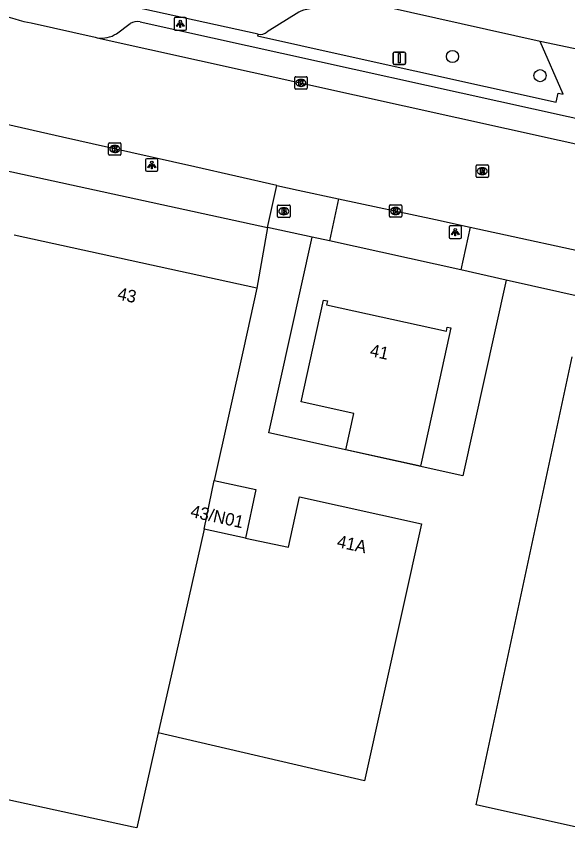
# Model space of a CAD drawing. Extents: x 162172 to 163187, y 382874 to 383684.
# Drawn here: x 162616.1 to 162660.4, y 383101.7 to 383167.1 of the extents above; entities that cross this region are included whole.
import ezdxf

# ---------------------------------------------------------------- set-up
doc = ezdxf.new("R2010")
doc.units = 0
for name, color, linetype in [('IMGEO_Boom', 7, 'Continuous'), ('IMGEO_Brandkraan', 7, 'Continuous'), ('IMGEO_Hek', 7, 'Continuous'), ('IMGEO_Kolk', 7, 'Continuous'), ('IMGEO_Lichtpunt', 7, 'Continuous'), ('IMGEO_Muur', 7, 'Continuous'), ('IMGEO_Pand', 7, 'Continuous'), ('IMGEO_Pand_nummerreeks', 7, 'Continuous'), ('IMGEO_Parkeervlak_open', 7, 'Continuous'), ('IMGEO_Rijbaan_lokaal_open', 7, 'Continuous'), ('IMGEO_Rioolput', 7, 'Continuous'), ('IMGEO_Verkeersbordpaal', 7, 'Continuous'), ('IMGEO_Voetpad_open', 7, 'Continuous')]:
    doc.layers.add(name, color=color, linetype=linetype)

msp = doc.modelspace()

# ---------------------------------------------------------------- linework, layer by layer
at = {"layer": 'IMGEO_Boom'}
for centre in [(162651.15, 383163.911), (162658.185, 383162.367)]:
    msp.add_circle(centre, 0.489, dxfattribs=at)
at = {"layer": 'IMGEO_Brandkraan'}
for p, q in [((162637.091, 383151.046), (162637.091, 383151.898)), ((162637.166, 383151.972), (162638.018, 383151.972)), ((162637.579, 383151.752), (162637.604, 383151.752)), ((162638.092, 383151.898), (162638.092, 383151.046)), ((162637.602, 383151.192), (162637.577, 383151.192)), ((162638.018, 383150.972), (162637.166, 383150.972))]:
    msp.add_line(p, q, dxfattribs=at)
for points in [[(162637.091, 383151.046), (162637.091, 383151.898)], [(162637.166, 383151.972), (162638.018, 383151.972)], [(162638.092, 383151.898), (162638.092, 383151.046)], [(162637.439, 383151.672), (162637.439, 383151.272), (162637.652, 383151.272)], [(162637.67, 383151.672), (162637.439, 383151.672)], [(162637.618, 383151.591), (162637.564, 383151.591), (162637.564, 383151.515)], [(162637.564, 383151.515), (162637.617, 383151.515)], [(162637.626, 383151.439), (162637.564, 383151.439), (162637.564, 383151.358)], [(162637.564, 383151.358), (162637.626, 383151.358)], [(162638.018, 383150.972), (162637.166, 383150.972)]]:
    msp.add_lwpolyline(points, dxfattribs=at)
for centre, radius, start, end in [((162637.168, 383151.896), 0.0765, 91.55205, 178.44795), ((162637.168, 383151.896), 0.0765, 91.55205, 178.44795), ((162638.016, 383151.896), 0.0765, 1.55205, 88.44795), ((162638.016, 383151.896), 0.0765, 1.55205, 88.44795), ((162637.619, 383151.553), 0.0379, 267.82845, 90.93552), ((162637.627, 383151.398), 0.0404, 269.87594, 90.50774), ((162637.658, 383151.523), 0.251, 268.66757, 293.53466), ((162637.674, 383151.527), 0.145, 59.4692, 91.53667), ((162637.699, 383151.574), 0.0922, 285.51372, 58.15012), ((162637.704, 383151.382), 0.105, 301.31148, 78.98903), ((162637.168, 383151.048), 0.0765, 181.55205, 268.44795), ((162637.168, 383151.048), 0.0765, 181.55205, 268.44795), ((162638.016, 383151.048), 0.0765, 271.55205, 358.44795), ((162638.016, 383151.048), 0.0765, 271.55205, 358.44795)]:
    msp.add_arc(centre, radius, start, end, dxfattribs=at)
for centre, major_axis, ratio, start_param, end_param in [((162637.578, 383151.472), (-0.387, 0.002), 0.722429, 4.712389, 7.853982), ((162637.603, 383151.472), (-0.39, 0.002), 0.717154, 1.570796, 4.712389)]:
    msp.add_ellipse(centre, major_axis=major_axis, ratio=ratio, start_param=start_param, end_param=end_param, dxfattribs=at)
at = {"layer": 'IMGEO_Hek'}
msp.add_lwpolyline([(162655.461, 383145.939), (162651.986, 383130.225), (162636.383, 383133.676), (162639.859, 383149.393)], dxfattribs=at)
at = {"layer": 'IMGEO_Kolk'}
for p, q in [((162638.47, 383161.355), (162638.47, 383162.207)), ((162638.545, 383162.281), (162639.397, 383162.281)), ((162639.471, 383162.207), (162639.471, 383161.355)), ((162638.958, 383162.061), (162638.983, 383162.061)), ((162639.397, 383161.281), (162638.545, 383161.281)), ((162638.981, 383161.501), (162638.956, 383161.501)), ((162623.58, 383156.976), (162624.432, 383156.976)), ((162623.505, 383156.05), (162623.505, 383156.902)), ((162623.993, 383156.756), (162624.018, 383156.756)), ((162624.506, 383156.902), (162624.506, 383156.05)), ((162624.432, 383155.976), (162623.58, 383155.976)), ((162624.016, 383156.196), (162623.991, 383156.196)), ((162646.076, 383151.066), (162646.076, 383151.918)), ((162646.151, 383151.992), (162647.003, 383151.992)), ((162646.564, 383151.772), (162646.589, 383151.772)), ((162647.077, 383151.918), (162647.077, 383151.066)), ((162646.587, 383151.212), (162646.562, 383151.212)), ((162647.003, 383150.992), (162646.151, 383150.992))]:
    msp.add_line(p, q, dxfattribs=at)
for points in [[(162638.47, 383161.355), (162638.47, 383162.207)], [(162638.545, 383162.281), (162639.397, 383162.281)], [(162639.471, 383162.207), (162639.471, 383161.355)], [(162638.791, 383161.981), (162638.914, 383161.981), (162638.914, 383161.83), (162639.044, 383161.981), (162639.208, 383161.981), (162639.062, 383161.83), (162639.215, 383161.581), (162639.063, 383161.581), (162638.978, 383161.745), (162638.914, 383161.678), (162638.914, 383161.581), (162638.791, 383161.581), (162638.791, 383161.981)], [(162639.397, 383161.281), (162638.545, 383161.281)], [(162623.58, 383156.976), (162624.432, 383156.976)], [(162623.505, 383156.05), (162623.505, 383156.902)], [(162623.826, 383156.676), (162623.949, 383156.676), (162623.949, 383156.525), (162624.079, 383156.676), (162624.243, 383156.676), (162624.097, 383156.525), (162624.25, 383156.276), (162624.098, 383156.276), (162624.013, 383156.44), (162623.949, 383156.373), (162623.949, 383156.276), (162623.826, 383156.276), (162623.826, 383156.676)], [(162624.506, 383156.902), (162624.506, 383156.05)], [(162624.432, 383155.976), (162623.58, 383155.976)], [(162646.076, 383151.066), (162646.076, 383151.918)], [(162646.151, 383151.992), (162647.003, 383151.992)], [(162647.077, 383151.918), (162647.077, 383151.066)], [(162646.397, 383151.692), (162646.52, 383151.692), (162646.52, 383151.541), (162646.65, 383151.692), (162646.814, 383151.692), (162646.668, 383151.541), (162646.821, 383151.292), (162646.669, 383151.292), (162646.584, 383151.456), (162646.52, 383151.389), (162646.52, 383151.292), (162646.397, 383151.292), (162646.397, 383151.692)], [(162647.003, 383150.992), (162646.151, 383150.992)]]:
    msp.add_lwpolyline(points, dxfattribs=at)
for centre, start, end in [((162638.547, 383162.205), 91.55205, 178.44795), ((162638.547, 383162.205), 91.55205, 178.44795), ((162639.395, 383162.205), 1.55205, 88.44795), ((162639.395, 383162.205), 1.55205, 88.44795), ((162638.547, 383161.357), 181.55205, 268.44795), ((162638.547, 383161.357), 181.55205, 268.44795), ((162639.395, 383161.357), 271.55205, 358.44795), ((162639.395, 383161.357), 271.55205, 358.44795), ((162623.582, 383156.9), 91.55205, 178.44795), ((162623.582, 383156.9), 91.55205, 178.44795), ((162624.43, 383156.9), 1.55205, 88.44795), ((162624.43, 383156.9), 1.55205, 88.44795), ((162623.582, 383156.052), 181.55205, 268.44795), ((162623.582, 383156.052), 181.55205, 268.44795), ((162624.43, 383156.052), 271.55205, 358.44795), ((162624.43, 383156.052), 271.55205, 358.44795), ((162646.153, 383151.916), 91.55205, 178.44795), ((162646.153, 383151.916), 91.55205, 178.44795), ((162647.001, 383151.916), 1.55205, 88.44795), ((162647.001, 383151.916), 1.55205, 88.44795), ((162646.153, 383151.068), 181.55205, 268.44795), ((162646.153, 383151.068), 181.55205, 268.44795), ((162647.001, 383151.068), 271.55205, 358.44795), ((162647.001, 383151.068), 271.55205, 358.44795)]:
    msp.add_arc(centre, 0.0765, start, end, dxfattribs=at)
for centre, major_axis, ratio, start_param, end_param in [((162638.957, 383161.781), (-0.387, 0.002), 0.722429, 4.712389, 7.853982), ((162638.982, 383161.781), (-0.39, 0.002), 0.717154, 1.570796, 4.712389), ((162623.992, 383156.476), (-0.387, 0.002), 0.722429, 4.712389, 7.853982), ((162624.017, 383156.476), (-0.39, 0.002), 0.717154, 1.570796, 4.712389), ((162646.563, 383151.492), (-0.387, 0.002), 0.722429, 4.712389, 7.853982), ((162646.588, 383151.492), (-0.39, 0.002), 0.717154, 1.570796, 4.712389)]:
    msp.add_ellipse(centre, major_axis=major_axis, ratio=ratio, start_param=start_param, end_param=end_param, dxfattribs=at)
at = {"layer": 'IMGEO_Lichtpunt'}
for p, q in [((162628.77, 383166.934), (162628.77, 383166.127)), ((162628.77, 383166.934), (162628.77, 383166.127)), ((162629.672, 383167.029), (162628.864, 383167.029)), ((162629.672, 383167.029), (162628.864, 383167.029)), ((162629.766, 383166.127), (162629.766, 383166.934)), ((162629.766, 383166.127), (162629.766, 383166.934)), ((162628.864, 383166.033), (162629.672, 383166.033)), ((162628.864, 383166.033), (162629.672, 383166.033)), ((162627.386, 383155.691), (162626.578, 383155.691)), ((162627.386, 383155.691), (162626.578, 383155.691)), ((162626.484, 383155.596), (162626.484, 383154.789)), ((162626.484, 383155.596), (162626.484, 383154.789)), ((162627.48, 383154.789), (162627.48, 383155.596)), ((162627.48, 383154.789), (162627.48, 383155.596)), ((162626.578, 383154.695), (162627.386, 383154.695)), ((162626.578, 383154.695), (162627.386, 383154.695)), ((162650.87, 383150.198), (162650.87, 383149.391)), ((162650.87, 383150.198), (162650.87, 383149.391)), ((162651.772, 383150.293), (162650.964, 383150.293)), ((162651.772, 383150.293), (162650.964, 383150.293)), ((162651.866, 383149.391), (162651.866, 383150.198)), ((162651.866, 383149.391), (162651.866, 383150.198)), ((162650.964, 383149.297), (162651.772, 383149.297)), ((162650.964, 383149.297), (162651.772, 383149.297))]:
    msp.add_line(p, q, dxfattribs=at)
for points in [[(162629.144, 383166.598), (162629.183, 383166.57), (162628.995, 383166.308), (162628.957, 383166.335), (162629.144, 383166.598)], [(162629.246, 383166.55), (162629.293, 383166.55), (162629.293, 383166.228), (162629.246, 383166.228), (162629.246, 383166.55)], [(162629.356, 383166.57), (162629.394, 383166.597), (162629.581, 383166.335), (162629.542, 383166.307), (162629.356, 383166.57)], [(162626.858, 383155.26), (162626.897, 383155.232), (162626.709, 383154.97), (162626.671, 383154.997), (162626.858, 383155.26)], [(162626.96, 383155.212), (162627.007, 383155.212), (162627.007, 383154.89), (162626.96, 383154.89), (162626.96, 383155.212)], [(162627.07, 383155.232), (162627.108, 383155.259), (162627.295, 383154.997), (162627.256, 383154.969), (162627.07, 383155.232)], [(162651.244, 383149.862), (162651.283, 383149.834), (162651.095, 383149.572), (162651.057, 383149.599), (162651.244, 383149.862)], [(162651.346, 383149.814), (162651.393, 383149.814), (162651.393, 383149.492), (162651.346, 383149.492), (162651.346, 383149.814)], [(162651.456, 383149.834), (162651.494, 383149.861), (162651.681, 383149.599), (162651.642, 383149.571), (162651.456, 383149.834)]]:
    msp.add_lwpolyline(points, dxfattribs=at)
for centre in [(162629.269, 383166.732), (162626.983, 383155.394), (162651.369, 383149.996)]:
    msp.add_circle(centre, 0.0994, dxfattribs=at)
for centre, start, end in [((162628.864, 383166.934), 90, 180), ((162628.864, 383166.934), 90, 180), ((162629.672, 383166.934), 0, 90), ((162629.672, 383166.934), 0, 90), ((162628.864, 383166.127), 180, 270), ((162628.864, 383166.127), 180, 270), ((162629.672, 383166.127), 270, 0), ((162629.672, 383166.127), 270, 360), ((162626.578, 383155.596), 90, 180), ((162626.578, 383155.596), 90, 180), ((162627.386, 383155.596), 0, 90), ((162627.386, 383155.596), 0, 90), ((162626.578, 383154.789), 180, 270), ((162626.578, 383154.789), 180, 270), ((162627.386, 383154.789), 270, 0), ((162627.386, 383154.789), 270, 360), ((162650.964, 383150.198), 90, 180), ((162650.964, 383150.198), 90, 180), ((162651.772, 383150.198), 0, 90), ((162651.772, 383150.198), 0, 90), ((162650.964, 383149.391), 180, 270), ((162650.964, 383149.391), 180, 270), ((162651.772, 383149.391), 270, 0), ((162651.772, 383149.391), 270, 360)]:
    msp.add_arc(centre, 0.0946, start, end, dxfattribs=at)
at = {"layer": 'IMGEO_Muur'}
msp.add_lwpolyline([(162636.279, 383150.172), (162635.424, 383145.306)], dxfattribs=at)
at = {"layer": 'IMGEO_Pand'}
for points in [[(162635.424, 383145.306), (162615.917, 383149.56)], [(162635.424, 383145.306), (162634.345, 383140.424), (162632.005, 383129.841)], [(162642.576, 383132.31), (162643.223, 383135.236), (162638.994, 383136.171), (162639.715, 383139.449), (162640.788, 383144.332), (162641.091, 383144.266), (162641.023, 383143.954), (162650.666, 383141.852), (162650.734, 383142.164), (162651.027, 383142.1), (162649.949, 383137.218), (162649.218, 383133.91), (162648.572, 383130.984), (162642.576, 383132.31)], [(162670.276, 383099.967), (162653.057, 383103.778), (162657.479, 383124.416), (162659.724, 383134.895), (162660.771, 383139.784)], [(162631.181, 383125.935), (162632.005, 383129.841)], [(162632.005, 383129.841), (162635.351, 383129.123), (162634.513, 383125.217)], [(162634.513, 383125.217), (162637.959, 383124.478), (162638.85, 383128.535), (162648.655, 383126.367), (162644.086, 383105.708), (162627.504, 383109.562)], [(162631.181, 383125.935), (162628.67, 383114.755), (162627.504, 383109.562)], [(162634.513, 383125.217), (162631.181, 383125.935)], [(162627.504, 383109.562), (162625.79, 383101.932), (162625.476, 383102), (162624.255, 383102.266), (162605.924, 383106.249)]]:
    msp.add_lwpolyline(points, dxfattribs=at)
at = {"layer": 'IMGEO_Parkeervlak_open'}
msp.add_lwpolyline([(162643.058, 383168.416), (162639.174, 383167.62), (162638.966, 383167.547), (162638.811, 383167.468), (162636.263, 383165.893)], dxfattribs=at)
msp.add_arc((162635.734, 383166.431), 0.755, 253.63617, 314.50898, dxfattribs=at)
at = {"layer": 'IMGEO_Rijbaan_lokaal_open'}
for points in [[(162658.204, 383165.105), (162643.449, 383168.407), (162643.217, 383168.426), (162643.058, 383168.416)], [(162616.709, 383166.727), (162617.288, 383166.603), (162622.419, 383165.446), (162622.598, 383165.402)], [(162622.598, 383165.402), (162709.068, 383146.272)], [(162661.881, 383164.326), (162658.204, 383165.105)], [(162637.042, 383153.547), (162630.442, 383155.04), (162623.509, 383156.587), (162619.796, 383157.416), (162614.715, 383158.574), (162611.71, 383159.259)], [(162637.042, 383153.547), (162638.752, 383153.16), (162641.979, 383152.473)], [(162641.979, 383152.473), (162649.778, 383150.811), (162652.581, 383150.202)], [(162652.581, 383150.202), (162664.161, 383147.688)]]:
    msp.add_lwpolyline(points, dxfattribs=at)
msp.add_arc((162624.884, 383198.452), 32.762, 250.15119, 255.55054, dxfattribs=at)
at = {"layer": 'IMGEO_Rioolput'}
for p, q in [((162653.043, 383154.268), (162653.043, 383155.12)), ((162653.118, 383155.194), (162653.97, 383155.194)), ((162654.044, 383155.12), (162654.044, 383154.268)), ((162653.554, 383154.414), (162653.529, 383154.414)), ((162653.531, 383154.974), (162653.556, 383154.974)), ((162653.97, 383154.194), (162653.118, 383154.194))]:
    msp.add_line(p, q, dxfattribs=at)
for points in [[(162653.043, 383154.268), (162653.043, 383155.12)], [(162653.118, 383155.194), (162653.97, 383155.194)], [(162654.044, 383155.12), (162654.044, 383154.268)], [(162653.632, 383154.892), (162653.38, 383154.894), (162653.38, 383154.494)], [(162653.38, 383154.494), (162653.504, 383154.494), (162653.504, 383154.656), (162653.515, 383154.656)], [(162653.558, 383154.813), (162653.504, 383154.813), (162653.504, 383154.732)], [(162653.504, 383154.732), (162653.556, 383154.732)], [(162653.562, 383154.627), (162653.633, 383154.494), (162653.773, 383154.494), (162653.708, 383154.62)], [(162653.97, 383154.194), (162653.118, 383154.194)]]:
    msp.add_lwpolyline(points, dxfattribs=at)
for centre, radius, start, end in [((162653.12, 383155.118), 0.0765, 91.55205, 178.44795), ((162653.12, 383155.118), 0.0765, 91.55205, 178.44795), ((162653.968, 383155.118), 0.0765, 1.55205, 88.44795), ((162653.968, 383155.118), 0.0765, 1.55205, 88.44795), ((162653.514, 383154.603), 0.0533, 26.02933, 88.69889), ((162653.54, 383154.921), 0.19, 274.7715, 282.96867), ((162653.564, 383154.717), 0.0964, 77.00612, 93.18647), ((162653.578, 383154.774), 0.0378, 276.66336, 79.67722), ((162653.631, 383154.782), 0.109, 350.36119, 89.41601), ((162653.629, 383154.782), 0.112, 277.58423, 350.98172), ((162653.613, 383154.567), 0.108, 29.51342, 73.79051), ((162653.12, 383154.27), 0.0765, 181.55205, 268.44795), ((162653.12, 383154.27), 0.0765, 181.55205, 268.44795), ((162653.968, 383154.27), 0.0765, 271.55205, 358.44795), ((162653.968, 383154.27), 0.0765, 271.55205, 358.44795)]:
    msp.add_arc(centre, radius, start, end, dxfattribs=at)
for centre, major_axis, ratio, start_param, end_param in [((162653.53, 383154.694), (-0.387, 0.002), 0.722429, 4.712389, 7.853982), ((162653.555, 383154.694), (-0.39, 0.002), 0.717154, 1.570796, 4.712389)]:
    msp.add_ellipse(centre, major_axis=major_axis, ratio=ratio, start_param=start_param, end_param=end_param, dxfattribs=at)
at = {"layer": 'IMGEO_Verkeersbordpaal'}
for p, q in [((162646.384, 383163.364), (162646.384, 383164.164)), ((162646.384, 383164.164), (162646.384, 383163.364)), ((162646.484, 383164.264), (162647.274, 383164.264)), ((162647.274, 383164.264), (162646.484, 383164.264)), ((162647.374, 383164.164), (162647.374, 383163.364)), ((162647.374, 383163.364), (162647.374, 383164.164)), ((162647.274, 383163.264), (162646.484, 383163.264)), ((162646.484, 383163.264), (162647.274, 383163.264))]:
    msp.add_line(p, q, dxfattribs=at)
msp.add_lwpolyline([(162646.804, 383164.139), (162646.954, 383164.139), (162646.954, 383163.389), (162646.804, 383163.389), (162646.804, 383164.139)], dxfattribs=at)
for centre, start, end in [((162646.484, 383164.164), 90, 180), ((162646.484, 383164.164), 90, 180), ((162647.274, 383164.164), 0, 90), ((162647.274, 383164.164), 360, 90), ((162646.484, 383163.364), 180, 270), ((162646.484, 383163.364), 180, 270), ((162647.274, 383163.364), 270, 0), ((162647.274, 383163.364), 270, 0)]:
    msp.add_arc(centre, 0.1, start, end, dxfattribs=at)
at = {"layer": 'IMGEO_Voetpad_open'}
for points in [[(162635.521, 383165.707), (162623.773, 383168.281)], [(162624.146, 383165.733), (162625.251, 383166.556)], [(162626.037, 383166.702), (162706.468, 383148.912)], [(162635.521, 383165.707), (162635.483, 383165.556), (162642.444, 383164.012), (162659.48, 383160.234), (162659.652, 383160.961), (162660.048, 383160.866), (162658.204, 383165.105)], [(162614.482, 383154.918), (162636.279, 383150.172)], [(162636.279, 383150.172), (162637.042, 383153.547)], [(162641.979, 383152.473), (162641.258, 383149.088)], [(162636.279, 383150.172), (162635.424, 383145.306)], [(162641.258, 383149.088), (162639.859, 383149.393), (162636.279, 383150.172)], [(162652.581, 383150.202), (162651.832, 383146.756)], [(162651.832, 383146.756), (162641.258, 383149.088)], [(162661.814, 383144.51), (162655.461, 383145.939), (162651.832, 383146.756)]]:
    msp.add_lwpolyline(points, dxfattribs=at)
for centre, radius, start, end in [((162625.852, 383165.508), 1.208, 81.1955, 119.85009), ((162622.907, 383167.743), 2.361, 262.48386, 301.65509)]:
    msp.add_arc(centre, radius, start, end, dxfattribs=at)

# ---------------------------------------------------------------- texts
at = {"layer": 'IMGEO_Pand_nummerreeks'}
for s, rotation, p in [('43', 347.6986, (162624.165, 383144.404)), ('41', 347.70433, (162644.449, 383139.85)), ('43/N01', 347.55, (162630.031, 383126.928)), ('41A', 347.55536, (162641.798, 383124.507))]:
    msp.add_text(s, height=1, rotation=rotation, dxfattribs=at).set_placement(p)

doc.saveas('drawing.dxf')
